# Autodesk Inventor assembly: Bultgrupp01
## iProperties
Created: 2001-12
Part Number: Bultgrupp01
Document SubType Name: Assembly
Designer: Tobben
Control State: 0
Master: False
Checked Out: False
Shininess: 64.0
Length Units: 11269
Angle Units: 11279
Time Units: 11290
Mass Units: 11283
Length Display Precision: 3
Angle Display Precision: 2
Density: 0.0
Volumn: 0.0
Area: 0.0
PropertySet Name: Model Information
Author: Tobben
